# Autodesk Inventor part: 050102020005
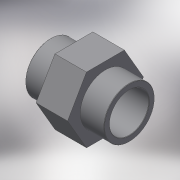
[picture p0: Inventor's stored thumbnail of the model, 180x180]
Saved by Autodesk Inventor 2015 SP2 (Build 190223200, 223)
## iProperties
Created: 2017-10
Part Number: 050102020005
Material: Generic
Description: PLASSON SOCKET ADAPTOR THR-CEM 20-1/2"
Document SubType Name: Modeling
Designer: KIM
Density: 1 g/cm^3
Appearance: Default
Author: KIM
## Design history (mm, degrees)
derived "050102.ipt"
feature "Solid1::050102.ipt"
tag "TaggingFeature1"
body "Solid1"
other parameters: "d0" = 36, "d3" = 18.631, "d4" = 18, "d5" = 16, "d6" = 17, "d7" = 24, "d8" = 23, "d10" = 11.9, "d13" = 0, "d14" = 0.2, "d15" = 12, "G_" = 18.631, "B_" = 12, "l_" = 16, "lt_" = 17, "H_" = 36
